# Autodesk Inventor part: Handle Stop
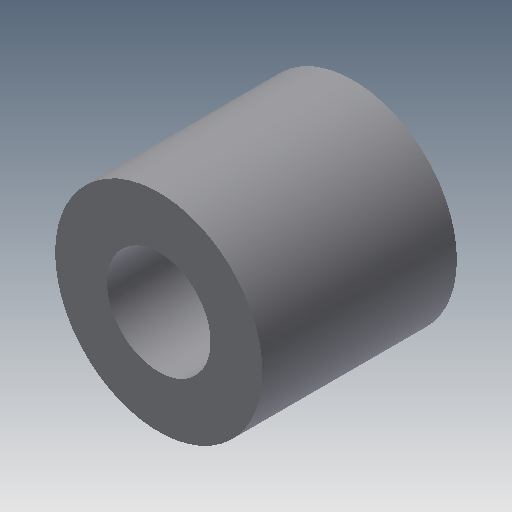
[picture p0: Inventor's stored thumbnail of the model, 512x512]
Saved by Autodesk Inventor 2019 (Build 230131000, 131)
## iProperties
Shininess: 77.0
Length Units: 11269
Angle Units: 11279
Time Units: 11290
Mass Units: 11283
Length Display Precision: 3
Angle Display Precision: 2
Compacted: True
Created: 2002-02
Part Number: Handle Stop
Document SubType Name: Modeling
Designer: ***
Density: 1 g/cm^3
Material: Generic
Mass: 2.36248 g
Surface Area: 14.8283 cm^2
Volume: 2.36248 cm^3
Appearance: Default
Density: 0.0
Volumn: 0.0
Area: 0.0
PropertySet Name: Model Information
Control State: 0
Master: False
Checked Out: False
Author: ***
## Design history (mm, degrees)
sketch "Sketch1"
  geometry: L1 (0, 0)-(0, -2); L2 (0, -2)-(8, -2); L3 (8, -2)-(8, 13); L4 (8, 13)-(4, 13); L5 (4, 13)-(4, 0); L6 (4, 0)-(0, 0)
  constraints: 12 end point, 4 parallel, 1 perpendicular, 1 vertical
  dimensions: "d0" = 16 diameter of L3 L1; "d1" = 8 diameter of L5 L1; "d2" = 2 distance of L1.start L1.end; "d3" = 15 distance of L2.end L3.end
revolve "Revolution1" sketch "Sketch1" stored, may be unused: angle "d4" = 90 deg
body "Solid1"
